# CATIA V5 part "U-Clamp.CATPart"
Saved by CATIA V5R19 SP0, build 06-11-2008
Part number: U-Clamp
Bounding box of the stored display mesh (mm): x -23 to 23, y -6.5 to 6.5, z -25 to 29
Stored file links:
  C:\Users\CADCIM\Desktop\CAT19\c16\Exercise-1\U-Clamp.CATPart
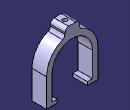
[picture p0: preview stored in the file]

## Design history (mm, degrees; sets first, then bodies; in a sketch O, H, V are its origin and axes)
Body1 (main body)
  Sketch1 on zx-plane, origin (0, 0, 0), H (-1, 0, 0), V (0, 0, 1)
    arc A1 centre (0, 0) radius 18 from (18, 0) to (-18, 0) ccw
    point P1 (-18, 0)
    point P2 (18, 0)
    line L1 (-18, 0) -> (-18, -22)
    point P3 (-18, -22)
    line L2 (-18, -22) -> (-13.5, -22)
    point P4 (-13.5, -22)
    line L3 (-13.5, -22) -> (-13.5, -25)
    point P5 (-13.5, -25)
    line L4 (-13.5, -25) -> (-23, -25)
    point P6 (-23, -25)
    line L5 (-23, -25) -> (-23, 0)
    point P7 (-23, 0)
    arc A2 centre (0, 0) radius 23 from (-23, 0) to (-6.5, 22.0624) cw
    point P9 (23, 0)
    point P10 (23, 0)
    point P11 (23, -25)
    line L6 (23, -25) -> (23, 0)
    point P12 (13.5, -25)
    line L7 (13.5, -25) -> (23, -25)
    point P13 (13.5, -22)
    line L8 (13.5, -22) -> (13.5, -25)
    point P14 (18, -22)
    line L9 (18, -22) -> (13.5, -22)
    point P15 (18, 0)
    line L10 (18, 0) -> (18, -22)
    line L11 (-6.5, 22.0624) -> (-6.5, 29)
    point P16 (-6.5, 29)
    line L12 (-6.5, 29) -> (6.5, 29)
    point P17 (6.5, 29)
    line L13 (6.5, 29) -> (6.5, 22.0624)
    point P18 (6.5, 22.0624)
    arc A3 centre (0, 0) radius 23 from (6.5, 22.0624) to (23, 0) cw
    distance L3 V = 13.5
    distance H L4 = 25
    distance V L5 = 23
    distance P16 P17 = 13
    distance L11 V = 6.5
    distance L7 L12 = 54
    distance L1 L5 = 5
    length L3 = 3
    coincidence: P1 H, P2 H, P7 H, A2 P18, A2 A3, P2 P15, P9 P10
    tangency: L1 A1, A2 L5
    horizontal: L2 H, L4 H, L12 H
    vertical: L3 V, L5 V, L11 V, L13 V
    concentricity: A2 A1
    symmetry: P7 P10 V, P6 P11 V, L5 L6 V, P5 P12 V, L4 L7 V, P4 P13 V, L3 L8 V, P3 P14 V, L2 L9 V, P1 P15 V, L1 L10 V
  Pad1: profile Sketch1, direction (0, -1, 0), length 6.5, mirrored extent
  Fillet1: radius 3.302, on 4 edges
  Sketch2 on face of Pad1, origin (-0.057, 2.6412, 29), H (1, 0, 0), V (0, 1, 0)
    point P1 (0.057, -2.6412)
    reference intersected line E1 through (0.057, 0) direction (0, 1) from yz-plane
    reference intersected line E2 through (0, -2.6412) direction (-1, 0) from zx-plane
    coincidence: E1 P1, E2 P1
  Hole1: placed by Sketch2, at (0, 0, 29) direction (0, 0, -1), diameter 4, depth 25.4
